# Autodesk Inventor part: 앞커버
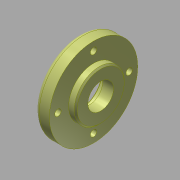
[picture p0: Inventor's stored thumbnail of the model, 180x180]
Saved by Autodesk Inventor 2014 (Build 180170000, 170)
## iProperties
Created: 2015-12
Part Number: 앞커버
Document SubType Name: Modeling
Designer: mdu
Density: 2.71 g/cm^3
Material: 알루미늄 6061
Mass: 70.9323 g
Surface Area: 93.9278 cm^2
Volume: 26.1743 cm^3
Appearance: 알루미늄 - 평지
Author: mdu
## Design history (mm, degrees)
sketch "스케치1"
  geometry: L1 (-7.5, 0)-(7.5, 0); L2 (-7.5, 0)-(-7.5, 31); L3 (-7.5, 31)-(2.5, 31); L4 (2.5, 31)-(2.5, 17.5); L5 (2.5, 17.5)-(7.5, 17.5); L6 (7.5, 17.5)-(7.5, 0); 2 further points
  constraints: 12 end point, 3 perpendicular, 1 coincident, 1 horizontal, 1 midpoint, 1 parallel
  dimensions: "d0" = 15 distance of L1.start L1.end; "d1" = 62 diameter of L3 L1; "d2" = 35 diameter of L5 L1; "d5" = 10 distance of L2.end L3.end
revolve "회전1" sketch "스케치1" stored, may be unused: angle "d6" = 90 deg
sketch "스케치2" dims "d42" = 50
  geometry: 3 further points
  constraints: 2 vertical alignment, 1 coincident, 2 other
hole "구멍1" sketch "스케치2" at (0, 25) diameter "d8" = 4.5; stored, may be unused: countersink angle "d12" = 90 deg, drill point angle "d14" = 118 deg; dims "d9" = 6, "d10" = 8, "d11" = 4.4, "d13" = 8
hole "구멍2" diameter "d20" = 18; stored, may be unused: countersink angle "d24" = 90 deg, drill point angle "d26" = 0 deg; dims "d18" = 10, "d19" = 10, "d21" = 6, "d22" = 8, "d23" = 4.4, "d25" = 8
hole "구멍3" diameter "d34" = 30; stored, may be unused: countersink angle "d38" = 90 deg, drill point angle "d40" = 0 deg; dims "d32" = 10, "d33" = 10, "d35" = 6, "d36" = 4, "d37" = 2, "d39" = 7.3
fillet "모깎기1" dims "d27" = 3, "d41" = 0.3
chamfer "모따기1" distance "d29" = 1; stored, may be unused: second distance "d30" = 2, angle "d31" = 45 deg
node "솔리드1"
pattern_circular "원형 패턴1" dims angle "d16" = 360 deg
